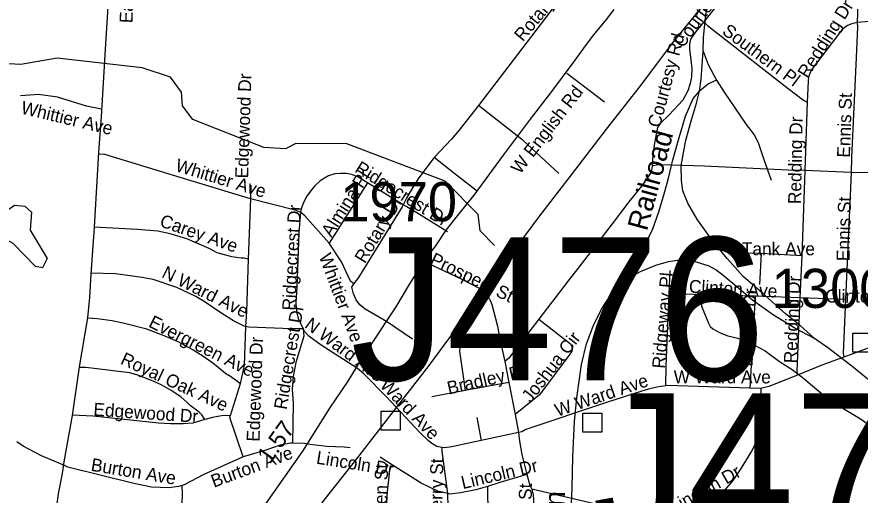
# Model space of a CAD drawing. Extents: x 1662474 to 1856135, y 779280 to 917889.
# Drawn here: x 1693341 to 1699530, y 797474 to 800984 of the extents above; entities that cross this region are included whole.
import ezdxf

# ---------------------------------------------------------------- set-up
doc = ezdxf.new("R2010")
doc.units = 0
for name, color, linetype in [('Cogo Default Point CELL', 7, 'Continuous'), ('Exist Hydrographic Misc Water Feature', 7, 'Continuous'), ('Exist Hydrographic Pond Under 1500 Sq Ft', 7, 'Continuous'), ('Exist Railroad Mainline', 7, 'Continuous'), ('Exist Railroad Mainline Label', 7, 'Continuous'), ('Exist Railroad Siding', 7, 'Continuous'), ('Exist Road Non-System Structure Non-Sys Other Attributed CELL', 7, 'Continuous'), ('Exist Road Non-System Structure Non-Sys Other Number Label', 7, 'Continuous'), ('Exist Road Non-System Type 51', 7, 'Continuous'), ('Exist Road Non-System Type 51 Label', 7, 'Continuous'), ('Exist Road Primary NC Label', 7, 'Continuous'), ('Exist Road Primary NC UnDivided 4 Lane Attributed', 7, 'Continuous'), ('Exist Road Secondary Mileage Tenths English Label', 7, 'Continuous'), ('Exist Road Secondary Type 51 Label', 7, 'Continuous'), ('Exist Road Secondary Type 51 Undivided 4 Lane Attributed', 7, 'Continuous')]:
    doc.layers.add(name, color=color, linetype=linetype)

msp = doc.modelspace()

# ---------------------------------------------------------------- linework, layer by layer
at = {"layer": 'Exist Hydrographic Misc Water Feature'}
for points in [[(1696847.9, 799307.2), (1696740.9, 799414.4), (1696725.9, 799532.9), (1696485.9, 799777.5), (1695763.9, 800051.4), (1695388.9, 800055.8), (1695312.9, 800014.5), (1695154.8, 800024.4), (1694631.8, 800232), (1694557.8, 800332), (1694550.8, 800430.5), (1694468.8, 800540.5), (1694260.9, 800610.4), (1693636.8, 800682.1), (1693369.8, 800635.1), (1693194.8, 800645.2), (1693026.8, 800579.7), (1692899.8, 800375.4), (1692756.8, 800217.5), (1692562.8, 800054.1)], [(1698367.2, 798904.6), (1698367.2, 798860.3), (1698418.5, 798736.2), (1698428.6, 798712.2), (1698450.5, 798693.7), (1698502.5, 798665.5), (1698560.3, 798643), (1698632.2, 798625.2), (1698760, 798572.5), (1698833.7, 798534.1), (1698937.6, 798455.6), (1699031.3, 798397.1), (1699117, 798328.9), (1699258.6, 798210.3), (1699340.5, 798150.4), (1699416, 798105.4), (1699525.9, 798039.1), (1699589.9, 797995.2), (1699703.4, 797900.9)]]:
    msp.add_lwpolyline(points, dxfattribs=at)
at = {"layer": 'Exist Hydrographic Pond Under 1500 Sq Ft'}
msp.add_lwpolyline([(1693215.8, 799528.7), (1693324.8, 799602), (1693399.9, 799593.9), (1693449.8, 799550.3), (1693439.9, 799419.2), (1693562.8, 799209.9), (1693528.8, 799141.6), (1693478.8, 799152.5), (1693313.9, 799320), (1693189.8, 799388.1), (1693215.8, 799528.7)], dxfattribs=at)
at = {"layer": 'Exist Railroad Mainline'}
for points in [[(1695532.7, 797355.6), (1695836.9, 797740.1), (1696137.3, 798128.2), (1696366.8, 798424.8), (1696552.5, 798677.8), (1696687.5, 798856.9), (1696858.6, 799090), (1697171.2, 799514.3), (1697410.9, 799824.9), (1697668.8, 800159.4), (1697920.8, 800480.2), (1698160.7, 800801), (1698313.9, 800989.9), (1698585.6, 801342.5), (1698859.8, 801700.9), (1699147.7, 802077.2), (1699411.8, 802426), (1699690.2, 802798.4)], [(1698378.2, 800731.6), (1698380.9, 800831.6), (1698397.8, 801001.6), (1698426.4, 801129.4)], [(1698350.6, 800439.7), (1698364.9, 800527.7), (1698378.2, 800731.6)], [(1697772.5, 799028.8), (1697814.9, 799082.4), (1697871.6, 799172.2), (1697946, 799297.7), (1698009.1, 799427.4), (1698053.6, 799553.2), (1698096.4, 799703), (1698123, 799800.9), (1698153.7, 799924.7), (1698202.6, 800098.3), (1698247.7, 800254.3), (1698306.2, 800385.7), (1698350.6, 800439.7)], [(1699196.7, 798624), (1699087.1, 798720.8), (1698983.4, 798803.6), (1698830.3, 798940.4), (1698670.9, 799079.5), (1698555.7, 799210.2), (1698452.6, 799334.7), (1698337.4, 799495.2), (1698266, 799617.8), (1698228.4, 799708.2), (1698218.8, 799782.2), (1698217.5, 799894.2), (1698250.7, 800078), (1698293.2, 800227.8), (1698330.1, 800349.8), (1698350.6, 800439.7)], [(1697404.3, 797224.4), (1697418.1, 797530.7), (1697421.3, 797754.5), (1697434.8, 798014.5), (1697451.8, 798188.5), (1697485, 798432.3), (1697521.9, 798584.2), (1697570.8, 798713.9), (1697631.4, 798839.3), (1697701.9, 798944.9), (1697772.5, 799028.8)], [(1699630.7, 798287.6), (1699481.2, 798410.5), (1699300.2, 798549.7), (1699196.7, 798624)]]:
    msp.add_lwpolyline(points, dxfattribs=at)
at = {"layer": 'Exist Railroad Siding'}
for points in [[(1698378.2, 800731.6), (1698415.7, 800635.3), (1698477, 800518.8)], [(1698477, 800518.8), (1698417, 800493.1), (1698350.6, 800439.7)], [(1698477, 800518.8), (1698532.6, 800430.4), (1698612, 800316.2), (1698695.2, 800195.3), (1698752.8, 800119), (1698782.5, 800062.9), (1698823.9, 799936.7), (1698877, 799786.3)], [(1699196.7, 798624), (1699050.9, 798699.2), (1698895.6, 798795.9), (1698739.9, 798905.1), (1698624.7, 799003.6), (1698525, 799086.1), (1698471.3, 799126.5), (1698421.4, 799154.8), (1698321.5, 799185.7), (1698223.7, 799199.8), (1698121.3, 799186.5), (1698029.2, 799159.2), (1697915, 799111.9), (1697826.7, 799062.5), (1697772.5, 799028.8)]]:
    msp.add_lwpolyline(points, dxfattribs=at)
at = {"layer": 'Exist Road Non-System Structure Non-Sys Other Attributed CELL'}
for points in [[(1699475.9, 798662.8), (1699614.9, 798662.8), (1699614.9, 798523.7), (1699475.9, 798523.7)], [(1696015.2, 798090.5), (1696154.2, 798090.5), (1696154.2, 797951.4), (1696015.2, 797951.4)], [(1697495.3, 798075.2), (1697634.3, 798075.2), (1697634.3, 797936.1), (1697495.3, 797936.1)]]:
    msp.add_lwpolyline(points, close=True, dxfattribs=at)
at = {"layer": 'Exist Road Non-System Type 51'}
for p, q in [((1697654.4, 800357.9), (1697376.9, 800567.9)), ((1697026, 800101), (1696729.4, 800333.9)), ((1699142, 800358.5), (1699124.9, 799855.4)), ((1699124.9, 799855.4), (1699102.1, 799229.6)), ((1699464.2, 799840.7), (1699124.9, 799855.4)), ((1699464.2, 799840.7), (1699422, 798910.5)), ((1695057.9, 799747.8), (1695055.6, 799648.5)), ((1695915, 799765.4), (1695632.6, 799322.5)), ((1696176.9, 799603.4), (1695915, 799765.4)), ((1695055.6, 799648.5), (1695038.9, 799206.8)), ((1698803.4, 799247.5), (1698609.4, 799253.2)), ((1698803.4, 799247.5), (1698792.4, 799020.4)), ((1699102.1, 799229.6), (1698803.4, 799247.5)), ((1699102.1, 799229.6), (1699088.6, 798922.5)), ((1698134.9, 799122.5), (1698125.8, 798952.5)), ((1698760.6, 798933), (1698125.8, 798952.5)), ((1698760.6, 798933), (1698721, 798259.6)), ((1699088.6, 798922.5), (1698760.6, 798933)), ((1699422, 798910.5), (1699088.6, 798922.5)), ((1696245.4, 798618.4), (1696053.1, 798747.5)), ((1696883.2, 798630.7), (1696923.4, 798454.1)), ((1699738.9, 798609.4), (1699411, 798487.1)), ((1696923.4, 798454.1), (1696952, 798300)), ((1694980.1, 798291.1), (1694905.9, 798056.7)), ((1696952, 798300), (1696632.1, 798241.2)), ((1696952, 798300), (1696997.4, 798065.1)), ((1698802.4, 798257.2), (1698721, 798259.6)), ((1696632.1, 798241.2), (1696387.4, 798196.1)), ((1696717.6, 798044.9), (1696747.9, 797874.5)), ((1696997.4, 798065.1), (1697023.1, 797933.1)), ((1697023.1, 797933.1), (1696747.9, 797874.5)), ((1696099, 797694.2), (1696007.9, 797753.2)), ((1696796.6, 797537), (1696799.2, 797055.7))]:
    msp.add_line(p, q, dxfattribs=at)
for points in [[(1697384.5, 801854.5), (1697434.4, 801548.2), (1697443.4, 801467.1), (1697439.9, 801393.9), (1697424.1, 801301.2), (1697404.2, 801235.6), (1697372.1, 801176.9), (1696729.4, 800333.9)], [(1699158.2, 801619.9), (1699485.2, 801374.5), (1699507.1, 801355.9), (1699522, 801334.4), (1699528.9, 801312.2), (1699529.9, 801286.2), (1699520.8, 801247.4), (1699509.4, 801162.7), (1699509.6, 801112.2), (1699512.9, 801083.9), (1699509.6, 800941.7)], [(1698605.8, 801247.7), (1698591.1, 801219.1), (1698558, 801169.5), (1698382.6, 800946.4)], [(1698382.6, 800946.4), (1698325.1, 800876.4), (1698285.9, 800820.7), (1698279.2, 800782.9), (1698279.2, 800750.1), (1698294, 800606), (1698292.4, 800543.5), (1698284.2, 800494.4), (1698266.1, 800441.9), (1698228.6, 800371.6), (1698129.6, 800264.8), (1698063.8, 800201), (1698043.9, 800171.4), (1698022.1, 800056.9), (1698008.6, 799971.6), (1698002.9, 799887.6)], [(1698382.6, 800946.4), (1698410.5, 800920.4), (1699002.4, 800458.2), (1699113.9, 800373.2), (1699142, 800358.5)], [(1699509.6, 800941.7), (1699468.5, 800932.5), (1699437.2, 800921.8), (1699397.4, 800890.5), (1699177.4, 800601.5), (1699163.8, 800576.1), (1699152.5, 800541.7), (1699148.9, 800512), (1699142, 800358.5)], [(1699509.6, 800941.7), (1699510.5, 800910.9), (1699503.6, 800739.6), (1699467.1, 799951.7), (1699464.2, 799840.7)], [(1699866.9, 800964.5), (1699570.1, 800948.8), (1699509.6, 800941.7)], [(1693963.1, 800306.2), (1693852.1, 800328.9), (1693639.1, 800394.4), (1693500.9, 800415.4), (1693368.9, 800403.6)], [(1696729.4, 800333.9), (1696586.1, 800150.4), (1696531, 800087.4), (1696404.5, 799952.2)], [(1697318.4, 799833.6), (1697054.9, 800078.7), (1697026, 800101)], [(1695055.6, 799648.5), (1694484.6, 799822.8), (1693985.9, 799975), (1693941.6, 799976.1)], [(1696404.5, 799952.2), (1696291.9, 799802.1), (1696245.4, 799729.4), (1696201.6, 799653.8), (1696176.9, 799603.4)], [(1696722.9, 799702.1), (1696544.9, 799839.6), (1696404.5, 799952.2)], [(1698002.9, 799887.6), (1697997.1, 799844.1), (1697934.9, 799754), (1697831.8, 799626.2), (1697710.2, 799464), (1697459.6, 799137.5), (1697387.4, 799047.5), (1697172.5, 798764.2)], [(1699124.9, 799855.4), (1699002.9, 799857.9), (1698386.9, 799887.9), (1698063.2, 799898.1), (1698042.5, 799897.1), (1698002.9, 799887.6)], [(1695915, 799765.4), (1695846, 799807), (1695798.8, 799826.5), (1695758.9, 799835.4), (1695714.8, 799835.4), (1695673.9, 799831.2), (1695629.4, 799817.9), (1695598.5, 799801.2), (1695568.6, 799780.2), (1695526.6, 799741.2), (1695496.9, 799706), (1695470.1, 799668.4), (1695448.1, 799627.5), (1695430.5, 799582.1), (1695422.1, 799551.2)], [(1699819.6, 799849.6), (1699780.9, 799844.9), (1699484.5, 799838.5), (1699464.2, 799840.7)], [(1695422.1, 799551.2), (1695383, 799564.2), (1695055.6, 799648.5)], [(1696176.9, 799603.4), (1696170.4, 799589.4), (1695844.6, 799064.9), (1695829.1, 799046.9), (1695815.2, 799023.6)], [(1696501.4, 799406), (1696277.5, 799546.7), (1696204.5, 799590), (1696176.9, 799603.4)], [(1695422.1, 799551.2), (1695409.8, 799398.1), (1695395.6, 799000.5), (1695387.8, 798882.1), (1695393, 798821), (1695407.1, 798769.5), (1695443.1, 798694.5)], [(1695632.6, 799322.5), (1695454.1, 799524.1), (1695422.1, 799551.2)], [(1695038.9, 799206.8), (1695008.5, 799213.1), (1694987.8, 799212.9), (1694919.5, 799222.5), (1694811.1, 799253), (1694752.9, 799283.4), (1694588.2, 799355.1), (1694465.6, 799391.6), (1694375.9, 799411.5), (1694226.4, 799423.1), (1693906.9, 799440.9)], [(1695815.2, 799023.6), (1695790.1, 799044.6), (1695725, 799186.4), (1695632.6, 799322.5)], [(1695038.9, 799206.8), (1695026.6, 798822.2), (1695019, 798711.5)], [(1696340.4, 799190), (1696358.4, 799175.9), (1696601.4, 799062.2), (1696733.4, 798993.4), (1696762.8, 798974), (1696784, 798953), (1696798.4, 798935.7), (1696818.1, 798898.4), (1696828.1, 798871.9), (1696867.8, 798714.7), (1696883.2, 798630.7)], [(1695019, 798711.5), (1695009.8, 798713.1), (1694932.4, 798753.5), (1694845.8, 798806.2), (1694717.1, 798893.9), (1694654.1, 798931.2), (1694515, 798998.9), (1694342.9, 799055.4), (1694261, 799071.9), (1694065.6, 799097.9), (1693885.9, 799102.1)], [(1696053.1, 798747.5), (1695898.1, 798839.6), (1695858.1, 798871.1), (1695832.6, 798906.5), (1695812.9, 798950.6), (1695800.1, 798999.2), (1695815.2, 799023.6)], [(1698125.8, 798952.5), (1698105.2, 798422), (1698102.1, 798276.9)], [(1699088.6, 798922.5), (1699066.9, 798381.1), (1699071.1, 798355.6)], [(1699422, 798910.5), (1699405, 798514.9), (1699411, 798487.1)], [(1694980.1, 798291.1), (1694961.2, 798307.9), (1694894.9, 798353.2), (1694884.4, 798356.2), (1694780.4, 798441.4), (1694705.6, 798494.2), (1694628.4, 798542.8), (1694525.9, 798598.2), (1694422.1, 798643.6), (1694296.1, 798691.9), (1694132.4, 798733.9), (1694041.6, 798752.2), (1693930, 798767.9), (1693861.8, 798773.5)], [(1697172.5, 798764.2), (1696951.1, 798478.2), (1696923.4, 798454.1)], [(1697172.5, 798764.2), (1697403.9, 798584), (1697412.9, 798567.7), (1697416.2, 798548), (1697413.9, 798529.1), (1697400.5, 798507.6), (1697177.4, 798209.2), (1696997.4, 798065.1)], [(1695019, 798711.5), (1695009.8, 798427), (1694980.1, 798291.1)], [(1695443.1, 798694.5), (1695356.2, 798693.4), (1695045.1, 798706.2), (1695019, 798711.5)], [(1695443.1, 798694.5), (1695448.6, 798640.9), (1695388.2, 798448.2), (1695368.4, 798345.7), (1695361.8, 798251.2), (1695368.4, 798146.2), (1695365.6, 797855.1)], [(1695840.5, 798402.4), (1695574.9, 798573.8), (1695483.2, 798640.4), (1695454.1, 798673.5), (1695443.1, 798694.5)], [(1696883.2, 798630.7), (1696617.9, 798585.5), (1696599.5, 798573.2), (1696591.4, 798560.4), (1696589.5, 798530.7), (1696632.1, 798241.2)], [(1699411, 798487.1), (1699250.4, 798427), (1699071.1, 798355.6)], [(1694720.9, 798027.9), (1694698.2, 798063), (1694679.6, 798083.2), (1694613.4, 798131.5), (1694591.6, 798154.1), (1694544.4, 798194.8), (1694474.9, 798241.8), (1694405.4, 798279.8), (1694358.1, 798303.4), (1694293.5, 798330.7), (1694222.6, 798356.2), (1694167.5, 798370.6), (1693888, 798406), (1693846, 798409.9), (1693804.9, 798409.9)], [(1696459.9, 797824.4), (1696423.1, 797832), (1696387.6, 797853.2), (1696358.9, 797874.5), (1696302.1, 797930.4), (1696053.1, 798196.1), (1695887.4, 798365.1), (1695840.5, 798402.4)], [(1699071.1, 798355.6), (1698861.4, 798271.7), (1698831.5, 798264.6), (1698802.4, 798257.2)], [(1698102.1, 798276.9), (1698037.2, 798266.1), (1697976.1, 798251.9), (1697928.6, 798237.5), (1697668.2, 798153), (1697076.1, 797954.9), (1697047.2, 797939.4), (1697023.1, 797933.1)], [(1698721, 798259.6), (1698115.2, 798278.4), (1698102.1, 798276.9)], [(1698802.4, 798257.2), (1698810, 797982.9), (1698803.1, 797941.2), (1698787.1, 797898.7), (1698732.2, 797797.4), (1698655.4, 797669.9), (1698595, 797580.9), (1698537, 797513.7), (1698479.5, 797468), (1698371.4, 797387.9), (1698343.4, 797371.4)], [(1694720.9, 798027.9), (1694632.4, 798002.9), (1694561.2, 797996.4), (1694468.1, 797996.1), (1694381.4, 798001.6), (1693902.4, 798052.8), (1693747.1, 798061.9)], [(1694905.9, 798056.7), (1694874.9, 798059.4), (1694843.4, 798055.4), (1694778, 798043.6), (1694720.9, 798027.9)], [(1695003.2, 797755.1), (1694905.1, 798042.5), (1694905.9, 798056.7)], [(1697023.1, 797933.1), (1697030.1, 797869.5), (1697047.9, 797771.9), (1697084.9, 797624.4)], [(1693691.1, 797690.6), (1693523.4, 797763.2), (1693388, 797834.1), (1693341, 797865.9)], [(1695365.6, 797855.1), (1695349.4, 797854.6), (1695272.8, 797841.2), (1695161.8, 797801), (1695003.2, 797755.1)], [(1695491.9, 797844.4), (1695452.6, 797853.5), (1695365.6, 797855.1)], [(1695787.4, 797822), (1695743.6, 797827), (1695615.9, 797830.2), (1695491.9, 797844.4)], [(1696747.9, 797874.5), (1696533.4, 797828.4), (1696480.9, 797820.5), (1696459.9, 797824.4)], [(1696459.9, 797824.4), (1696460.9, 797796.9), (1696501.1, 797485)], [(1695003.2, 797755.1), (1694714.8, 797624.9), (1694568.6, 797549.9), (1694555.8, 797545.7)], [(1694555.8, 797545.7), (1694528.4, 797536.5), (1694456, 797527.2), (1694328.4, 797531.2), (1694200.9, 797559.6), (1693716.6, 797679), (1693691.1, 797690.6)], [(1696099, 797694.2), (1696085.4, 797678.8), (1696077.5, 797653.5), (1696060.4, 797501.6), (1696052.5, 797379.8), (1696056.5, 797213.4), (1696073.5, 796987.4), (1696072.5, 796907.1)], [(1696501.1, 797485), (1696430.8, 797503.4), (1696308.4, 797561.7), (1696099, 797694.2)], [(1697084.9, 797624.4), (1696886.6, 797566.7), (1696796.6, 797537)], [(1697084.9, 797624.4), (1697107.1, 797547.8), (1697120.8, 797517.1)], [(1694548.4, 797174.6), (1694556.5, 797486.6), (1694555.8, 797545.7)], [(1696796.6, 797537), (1696708.9, 797513.7), (1696598.4, 797491.9), (1696521.6, 797480.9), (1696501.1, 797485)], [(1697120.8, 797517.1), (1697130.5, 797476.1), (1697133.6, 797439.9), (1697127.1, 797167.8), (1697128.1, 797057.8)], [(1698343.4, 797371.4), (1698311, 797351.7), (1698237.9, 797323.1), (1698165.1, 797305), (1698084, 797299.2), (1698042.8, 797299.2), (1698001.6, 797306.4), (1697623.6, 797399.8), (1697120.8, 797517.1)], [(1696501.1, 797485), (1696505.6, 797387.9), (1696513.4, 796694.8)]]:
    msp.add_lwpolyline(points, dxfattribs=at)
at = {"layer": 'Exist Road Primary NC UnDivided 4 Lane Attributed'}
msp.add_lwpolyline([(1693594, 797086.5), (1693648, 797483.3), (1693676.4, 797632.3), (1693689.7, 797718.1), (1693749.5, 798057.9), (1693801.8, 798415.1), (1693863.3, 798774.6), (1693877.5, 798926), (1693887.6, 799095.7), (1693911, 799439.6), (1693943.7, 799990.2), (1693962.7, 800250.4), (1693991.1, 800746.2), (1694051.2, 801684.4)], dxfattribs=at)
at = {"layer": 'Exist Road Secondary Type 51 Undivided 4 Lane Attributed'}
msp.add_lwpolyline([(1695168.4, 797409.3), (1695441.3, 797796.2), (1695638.1, 798111.8), (1695772.6, 798309.3), (1695850, 798435.5), (1695968.7, 798617.7), (1696056.4, 798753.6), (1696124.4, 798856.6), (1696225.2, 799025.4), (1696339.3, 799202.9), (1696417.3, 799304.6), (1696493.1, 799418.2), (1696556.3, 799499), (1696697.8, 799675.8), (1696913.1, 799968.7), (1697111.4, 800233.9), (1697268, 800436), (1697438.6, 800667), (1697502.3, 800754.7), (1697574.1, 800850.3), (1697661.7, 800953.8), (1697725.5, 801037.5)], dxfattribs=at)

# ---------------------------------------------------------------- texts
at = {"layer": 'Cogo Default Point CELL'}
for s, p in [('1970', (1695714.9, 799483.5)), ('1300', (1698881.7, 798847.5))]:
    msp.add_text(s, height=288, dxfattribs=at).set_placement(p)
at = {"layer": 'Exist Railroad Mainline Label'}
for s, rotation, p in [('Railroad', 74.79884, (1697964.8, 799406.4)), ('Denton', 88.04184, (1697342.4, 796855.1))]:
    msp.add_text(s, height=150, rotation=rotation, dxfattribs=at).set_placement(p)
at = {"layer": 'Exist Road Non-System Structure Non-Sys Other Number Label'}
for s, p in [('J476', (1695790.1, 798315.5)), ('J477', (1697564.8, 797172.3))]:
    msp.add_text(s, height=1049.86, dxfattribs=at).set_placement(p)
at = {"layer": 'Exist Road Non-System Type 51 Label'}
for s, rotation, p in [('Courtesy Rd', 53.7623, (1698229.9, 800750.3)), ('Rotary Dr', 50.1655, (1697055.3, 800796.7)), ('Redding Dr', 57.80436, (1699144.7, 800526.3)), ('Southern Pl', 323.36496, (1698511, 800864.2)), ('Courtesy Rd', 75.02012, (1698060.7, 800165.7)), ('Edgewood Dr', 88.09135, (1695038.3, 799797.1)), ('Ennis St', 88.12212, (1699455.5, 799949.6)), ('Whittier Ave', 346.52947, (1693365.5, 800275.4)), ('Redding Dr', 88.91266, (1699096.5, 799609.1)), ('Whittier Ave', 343.03519, (1694498.1, 799854.4)), ('Ridgecrest Dr', 328.22598, (1695814.8, 799850.6)), ('Almina Pl', 57.56848, (1695649.2, 799361.2)), ('Rotary Dr', 58.92689, (1695895.1, 799168.7)), ('Ennis St', 88.56326, (1699452.1, 799190.1)), ('Ridgecrest Dr', 86.67912, (1695382.9, 798826.2)), ('Carey Ave', 340.62248, (1694383.1, 799448.8)), ('Whittier Ave', 290.68472, (1695556.4, 799227)), ('Prospect St', 334.12089, (1696366.4, 799172.4)), ('N Ward Ave', 333.69196, (1694397.6, 799075.7)), ('Ridgeway Pl', 84.99015, (1698097.5, 798400)), ('Redding Dr', 87.44976, (1699065.3, 798440)), ('Clinton Ave', 356.75624, (1698271.9, 798960.1)), ('Lincoln Dr', 86.90622, (1698740.1, 798416.4)), ('Ridgecrest Dr', 80.54294, (1695321, 798097.2)), ('Evergreen Ave', 333.56514, (1694301.4, 798712.8)), ('N Ward Ave', 323.11451, (1695446.6, 798709.1)), ('Edgewood Dr', 88.09135, (1695122.3, 797865.1)), ('Joshua Cir', 52.22511, (1697112.9, 798146.7)), ('Royal Oak Ave', 335.21589, (1694094.8, 798439.9)), ('W Ward Ave', 313.73609, (1695892.9, 798387)), ('Bradley Pl', 12.88206, (1696511.3, 798212)), ('W Ward Ave', 359.93976, (1698162, 798294.7)), ('W Ward Ave', 18.74357, (1697309.2, 798048.1)), ('Edgewood Dr', 356.0468, (1693900.9, 798057.6)), ('Burton Ave', 20.48808, (1694787.4, 797527.7)), ('Lincoln Dr', 350.92031, (1695534.6, 797705.5)), ('Burton Ave', 350.58752, (1693880.4, 797653.1)), ('Van Buren St', 88.10231, (1696041.6, 796946.8)), ('Wrightenberry St', 89.03839, (1696455.4, 796789.3)), ('Lincoln Dr', 13.24776, (1696614.6, 797517.5)), ('Lincoln Dr', 29.43152, (1698166.4, 797335.6)), ('Prospect St', 89.03839, (1697111.1, 796901.5))]:
    msp.add_text(s, height=95, rotation=rotation, dxfattribs=at).set_placement(p)
for s, p in [('Tank Ave', (1698662, 799234.2)), ('Clinton Ave', (1699274.1, 798887.2))]:
    msp.add_text(s, height=95, dxfattribs=at).set_placement(p)
at = {"layer": 'Exist Road Primary NC Label'}
msp.add_text('East Chester Dr.', height=95, rotation=87.36766, dxfattribs=at).set_placement((1694189.3, 800936.2))
at = {"layer": 'Exist Road Secondary Mileage Tenths English Label'}
msp.add_text('1.57', height=125, rotation=54.45184, dxfattribs=at).set_placement((1695198.3, 797696))
at = {"layer": 'Exist Road Secondary Type 51 Label'}
msp.add_text('W English Rd', height=95, rotation=52.44464, dxfattribs=at).set_placement((1697034, 799823.4))

doc.saveas('drawing.dxf')
